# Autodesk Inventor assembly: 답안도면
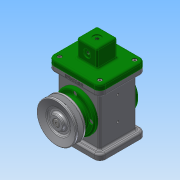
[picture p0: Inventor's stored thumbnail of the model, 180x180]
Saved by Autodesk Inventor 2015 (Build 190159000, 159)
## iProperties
Created: 2017-08
Part Number: 답안도면
Document SubType Name: Assembly
Designer: owner
Author: owner
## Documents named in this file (16)
- C:\Users\owner\Desktop\470807V1008\답안도면.iam
- C:\Users\owner\Desktop\470807V1008\1.본체.ipt
- C:\Users\owner\Desktop\470807V1008\뒤커버.ipt
- C:\Users\owner\Desktop\470807V1008\앞커버.ipt
- C:\Users\owner\Desktop\470807V1008\베어링 17 x 40 x 12.ipt
- C:\Users\owner\Desktop\470807V1008\링크.ipt
- C:\Users\owner\Desktop\470807V1008\슬라이더.ipt
- C:\Users\owner\Desktop\470807V1008\클레비스 핀 6 x 22.ipt
- 클레비스 핀 6 x 22.ipt
- C:\Users\owner\Desktop\470807V1008\편심축.ipt
- C:\Users\owner\Desktop\470807V1008\오일 실 17 30 8.ipt
- C:\Users\owner\Desktop\470807V1008\V-벨트풀리.ipt
- C:\Users\owner\Desktop\470807V1008\키 4 x 4 x 12.ipt
- C:\Users\owner\Desktop\470807V1008\볼트 M4 x 10.ipt
- C:\Users\owner\Desktop\470807V1008\덮개.ipt
- C:\Users\owner\Desktop\470807V1008\볼트 M4 x 8.ipt
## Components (2 placed, 2 different names)
1. 1.본체:1
2. V-벨트풀리:2 — 플러쉬:2, 각도:1
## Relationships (2: Flush 1, Angle 1)
- 플러쉬:2 [Flush]: V-벨트풀리:2
- 각도:1 [Angle]: V-벨트풀리:2
